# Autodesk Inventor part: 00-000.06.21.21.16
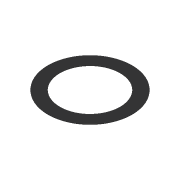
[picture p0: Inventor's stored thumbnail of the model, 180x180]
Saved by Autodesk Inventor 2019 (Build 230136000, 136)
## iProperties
Created: 2019-01
Part Number: 00-000.06.21.21.16
Material: Rubber
Document SubType Name: Modeling
Designer: m.vorobev
Density: 0.93 g/cm^3
Appearance: Rubber - Black
Author: m.vorobev
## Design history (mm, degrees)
sketch "Sketch1"
  geometry: L1 (50, 0.5)-(70, 0.5); L2 (70, 0.5)-(70, -0.5); L3 (70, -0.5)-(50, -0.5); L4 (50, -0.5)-(50, 0.5); L5 (0, 0)-(0, 3.769); 1 further point
  constraints: 10 end point, 2 parallel, 1 horizontal, 1 horizontal alignment, 1 midpoint, 1 perpendicular, 1 vertical
  dimensions: "d0" = 1 distance of L1.end L2.end; "d1" = 140 diameter of L2 L5; "d2" = 100 diameter of L4 L5
revolve "Revolution1" sketch "Sketch1" stored, may be unused: angle "d3" = 90 deg
body "Solid1"
